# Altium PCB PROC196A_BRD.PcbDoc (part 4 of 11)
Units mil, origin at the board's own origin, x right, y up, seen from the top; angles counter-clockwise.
Board outline 3346.45 x 4921.26 mil, 8 copper layers (Top Layer, GND1, SIG1, PWR1, PWR2, SIG2, GND2, Bottom Layer), stack 54.534 mil thick; 736 components, 498 nets, 3030 pads, 1279 vias.
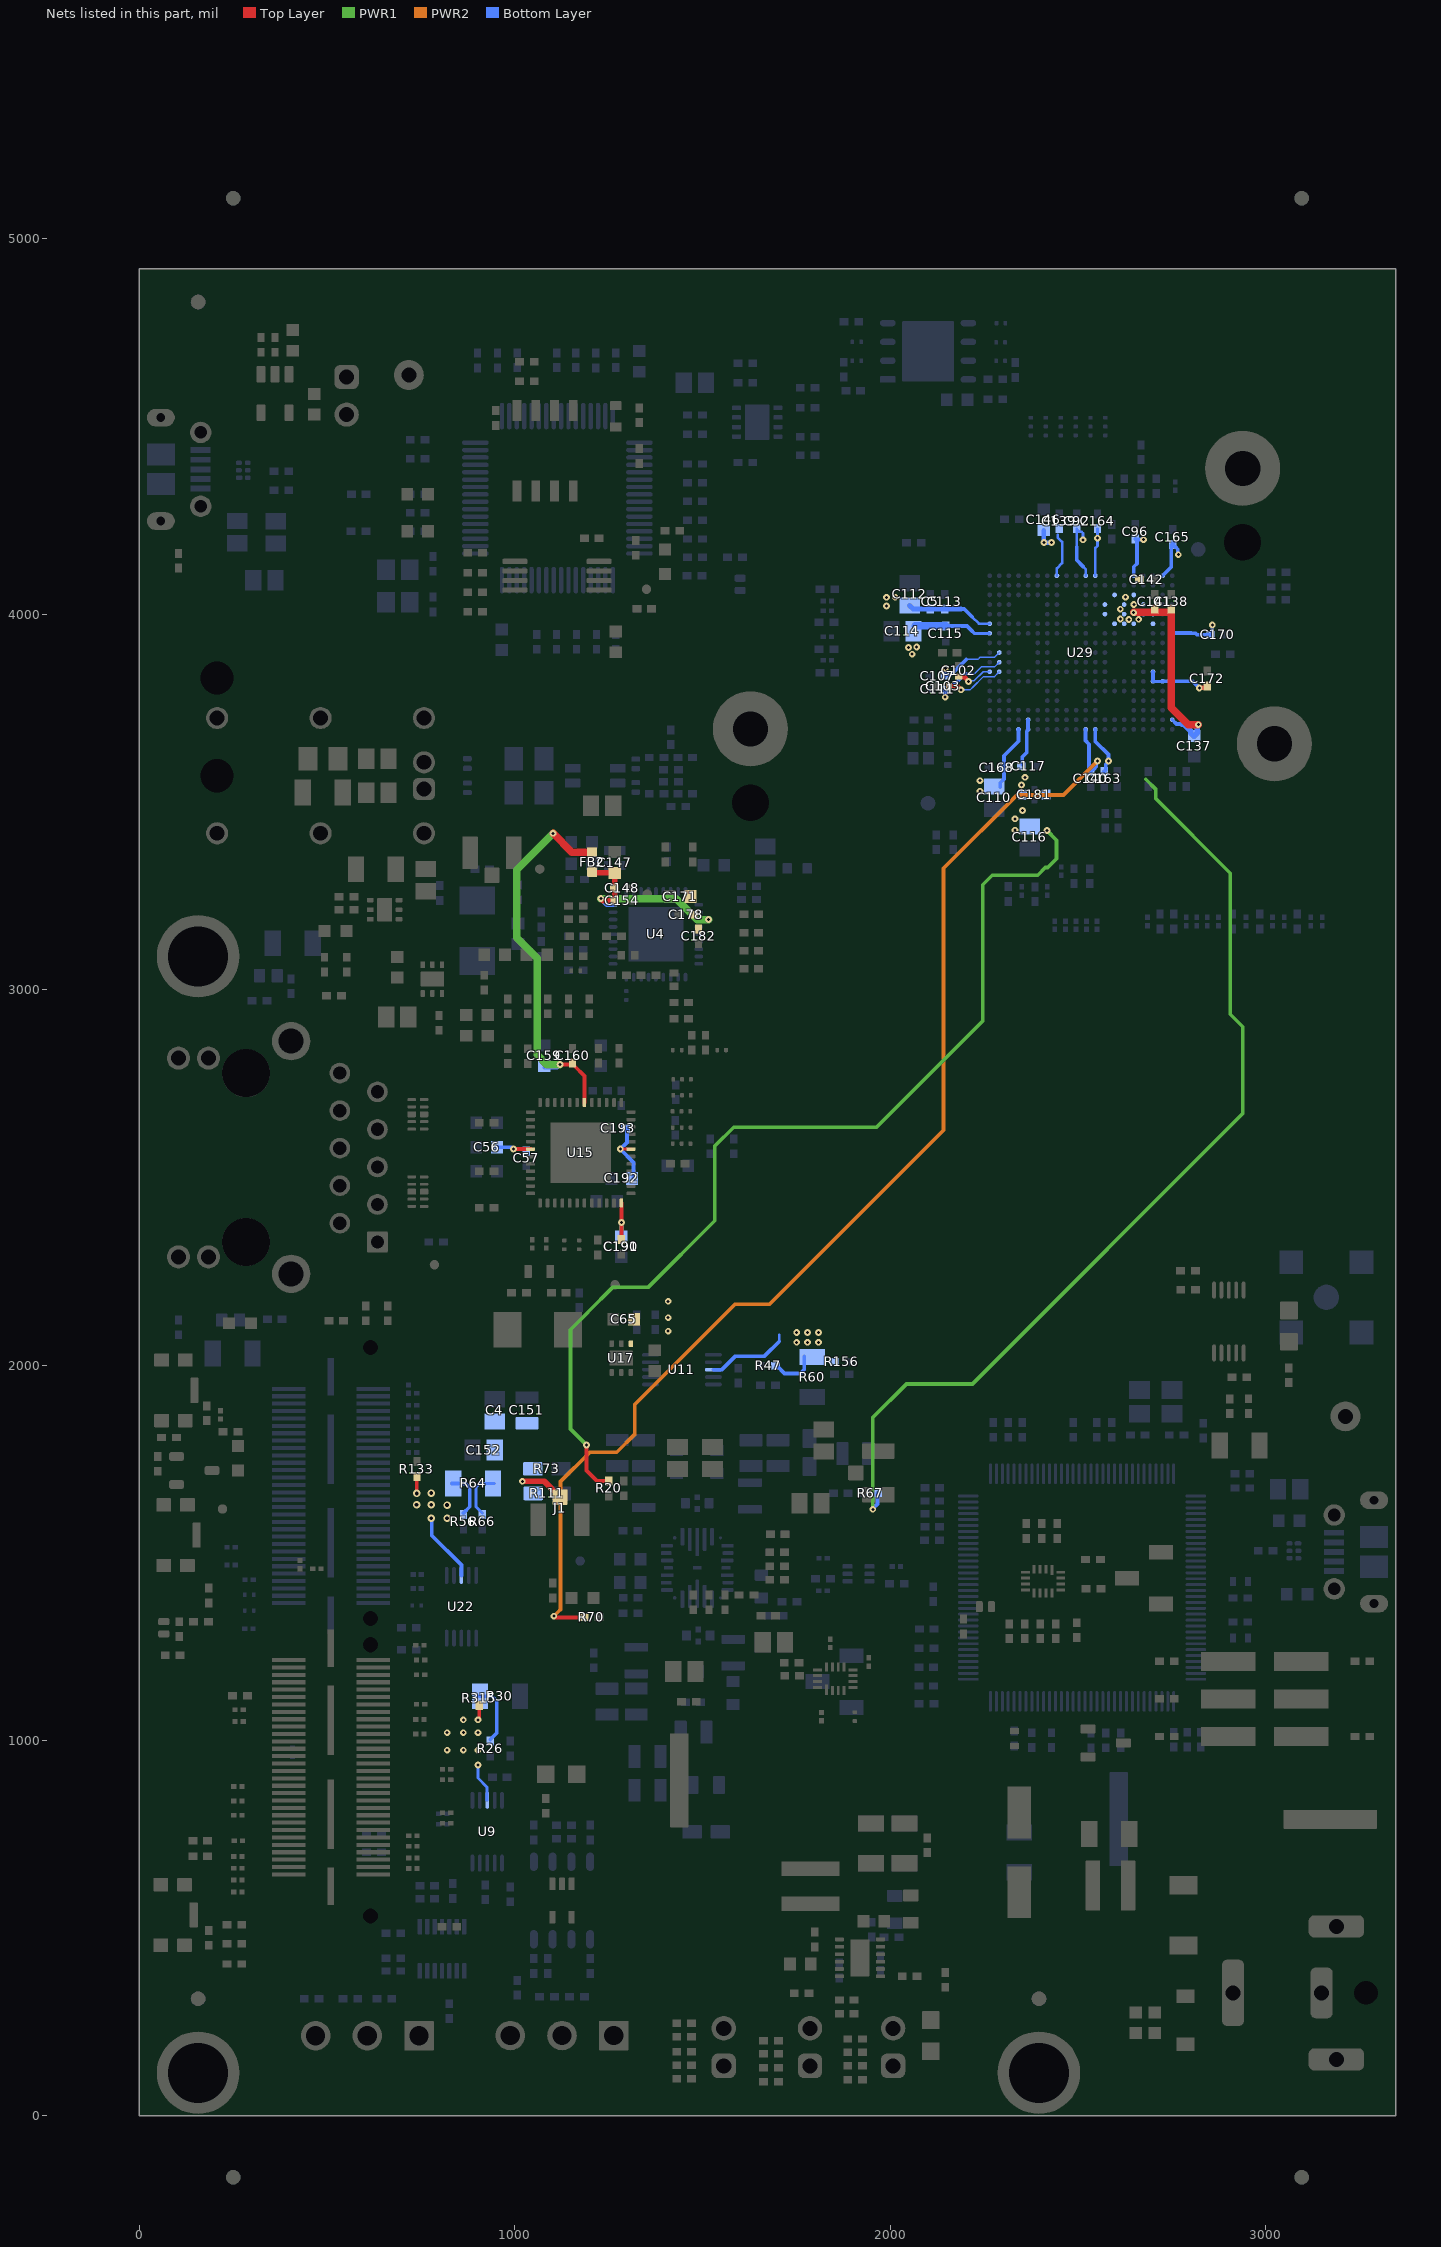
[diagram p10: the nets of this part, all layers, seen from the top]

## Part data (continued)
J9: library part CMP-0088394-1, "RJ45 Connector with 1000 Base-TX Inetgrated Magnetic", Manufacturer=LINK-PP, Operating Temperature Range="-40°C to +85°C"
J12: library part CMP-0079472-1, "DC POWER JACK, R/A, TH", Color=Black, Current_A=8A, Manufacturer="CUI Inc.", Supplier Part Number 1=CP-063AH-ND, Voltage_V=24V
J13: library part CMP-0055823-2, "Connector, SMA Jack, Vertical, Gold, SMD", Color=Gold, Manufacturer="Cinch Connectivity"
J14: library part CMP-0055788-1, "UMC Straight Jack Receptacle, 50 Ohm, Gold, SMT", Manufacturer="Cinch Connectivity", Supplier Part Number 1=J983CT-ND
J16: library part CMP-0075648-2, "Header, 2.54mm, 3x2, Gold, SMT", Color=Black, Current_A=4.9A, Manufacturer=Samtec, Supplier Part Number 1=TSM-103-01-L-DV-ND, Voltage_V=475V
J17 J18 J20 P1: library part CMP-0075405-3, "Header, 100mil, 2x1, Gold, TH", Color=Black, Current_A=6.3A, Manufacturer=Samtec, Supplier Part Number 1=SAM1029-02-ND, Voltage_V=550V
J19: library part CMP-0075524-1, "Receptacle, 0.5 mm, 30x2, Gold, TH", Color=Black, Manufacturer=Samtec, PartNumber=QSH-030-01-L-D-A, Supplier Part Number 1=SAM8180-ND
J21 J22 J23: library part CMP-0084373-1, "Header, 1x1, Gold, SMT", Color=Black, Current_A=3A, Manufacturer="Sullins Connector Solutions"
L1: library part CMP-0081093-1, "Inductor, Shielded, Metal Composite, 1.5 µH, 2.3 A, 0.11 ohm, AEC-Q200 Grade 0, SMD", Manufacturer=TDK, Supplier Part Number 1=445-174575-1-ND, Value1="0.11 ohm", Value2=2.3A, ValueDisplayed=1.5µH
L2 L8 L9: library part CMP-0091696-1, "240nH Shielded Thin Film Inductor 5A 23mOhm Max 0806 (2016 Metric)", Digikey Part Number=445-181484-1-ND, Manufacturer=TDK, Mouser Part Number=810-TFM201610ALMAR24, Operating Temperature Range="-55°C to +150°C", Test Frequency=1MHz, Tolerance_%=20%
L3 L4: library part CMP-0081523-1, "Ferrite Bead, 600 ohm @ 100 MHz, 0.3 A, 0402", Manufacturer=MuRata, Supplier Part Number 1=490-3998-1-ND, Value1="0.7 ohm", Value2=0.3A, ValueDisplayed="600 ohm"
L5: library part CMP-0089502-2, "Power Inductor (SMD), 4.7 µH, 5.1 A, Shielded, 4.5 A, XAL40xx Series, 4mm x 4mm x 3.1mm", Manufacturer=Coilcraft, Mouser Part Number=994-XAL4030-472MEC, Operating Temperature Range="to +165°C", Self Resonant Frequency=36MHz, Test Frequency=1MHz, Tolerance_%=20%
L6: library part CMP-0120010-1, "Ultra-Low Loss Shielded Power Inductors 2.2µH ±20% 7.8A 22.1mOhms", Manufacturer=Coilcraft, Value1="0.0201 ohm", Value2=6.1A, ValueDisplayed=2.2uH
L7: library part CMP-0089334-1, "200µH @ 100kHz 2 Line Common Mode Choke Surface Mount 70mA DCR 5.5Ohm", Digikey Part Number=445-174934-1-ND, Impedance At Frequency="9.5kΩ @ 10MHz", Manufacturer=TDK, Mouser Part Number=810-ACT1210L-2012P00, Operating Temperature Range="-40°C to +125°C", Test Frequency=100kHz, Tolerance_%=-10/30%
L10: library part CMP-0089947-1, "100 Ohms @ 100MHz 1 Power Line Ferrite Bead 0805 (2012 Metric) 4A 20mOhm", Digikey Part Number=445-172903-1-ND, Impedance At Frequency="100Ω @ 100MHz", Manufacturer=TDK, Mouser Part Number=810-MPZ2012S101ATD25, Operating Temperature Range="-55°C to +125°C", Test Frequency=100MHz, Tolerance_%=25%
LBL1: library part CMP-0003625-1, "Thermal Transfer Printable Labels, 0.650\" W x 0.200\" H - 10,000 per roll", Manufacturer=Brady, Supplier Part Number 1=97C5133
Logo1: library part CMP-0074838-1, "Texas Instrument Corporate Signature"
LOGO2: library part CMP-0074844-1
Logo3: library part CMP-0074847-1, "FCC_disclaimer"
Logo4: library part CMP-0074769-1
Logo5: library part CMP-0093808-1, Manufacturer="Texas Instruments", Operating Temperature Range=to
NT1: library part CMP-0078142-4, "Single point connection between nets.", Manufacturer=N/A
NT2 NT3 NT4: library part CMP-0078142-3, "Single point connection between nets.", Manufacturer=N/A
Q1: library part CMP-0000947-2, "MOSFET, N-CH, 100 V, 0.17 A, SOT-23", Alternate Manufacturer=None, Manufacturer="Fairchild Semiconductor", Supplier Part Number 1=BSS123NCT-ND, Value1=1, Value2="1.8 nC"
R1 R3 R4 R5 R6 R11 R12 R13 R14 R16 R17 R20 R21 R22 R23 R25 R27 R29 R31 R33 R35 R37 R50 R51 R54 R57 R58 R59 R61 R62 R63 R67 R70 R71 R75 R76 R78 R88 R90 R95 R107 R109 R113 R117 R128 R129 R131 R136 R146 R148 R149 R150 R151 R152 R153 R158 R160 R162 R164 R166 R167 R176 R181 R185 R186 R190 R209 R213 R214 R233 R246 R259 R269 R291 R295 R297 R316 R330 R353 R354 R355 R356 R357 R358 R359 R360 R367 R400 R401 R419: library part CMP-0026992-3, "RES, 0, 5%, 0.1 W, AEC-Q200 Grade 0, 0402", Manufacturer=Panasonic, Power_W=100mW, Supplier Part Number 1=P0.0JCT-ND, TempCo="600 ppm/C", Tolerance_%=5%, Value2=0.1W, Value_Code=0000, ValueDisplayed=0
R2: library part CMP-0026555-2, "RES, 7.50 k, 1%, 0.063 W, AEC-Q200 Grade 0, 0402", Manufacturer=Vishay-Dale, Power_W=63mW, Supplier Part Number 1=541-7.50KLCT-ND, TempCo="100 ppm/C", Tolerance_%=1%, Value2=0.063W, Value_Code=7k50, ValueDisplayed=7.50k
R7 R8 R9 R10 R18 R19 R41 R43 R46 R49 R86 R102 R106 R125 R155 R157 R177 R184 R187 R201 R210 R222 R250 R251 R264 R271 R272 R273 R283 R296 R299 R301 R303 R305 R309 R310 R312 R314 R326 R335 R350 R409 R416 R417 R418: library part CMP-0025958-3, "RES, 10.0 k, 1%, 0.063 W, AEC-Q200 Grade 0, 0402", Manufacturer=Vishay-Dale, Power_W=63mW, Supplier Part Number 1=541-10.0KLCT-ND, TempCo="100 ppm/C", Tolerance_%=1%, Value2=0.063W, Value_Code=10k0, ValueDisplayed=10.0k
R15 R24 R85 R87: library part CMP-0026491-2, "RES, 61.9, 1%, 0.063 W, AEC-Q200 Grade 0, 0402", Manufacturer=Vishay-Dale, Power_W=63mW, Supplier Part Number 1=541-61.9LCT-ND, TempCo="100 ppm/C", Tolerance_%=1%, Value2=0.063W, Value_Code=61R9, ValueDisplayed=61.9
R26 R32 R36 R47 R56 R65 R66 R268 R348 R352 R362: library part CMP-0025964-3, "RES, 10.2, 1%, 0.063 W, AEC-Q200 Grade 0, 0402", Manufacturer=Vishay-Dale, Power_W=63mW, Supplier Part Number 1=541-10.2LCT-ND, TempCo="100 ppm/C", Tolerance_%=1%, Value2=0.063W, Value_Code=10R2, ValueDisplayed=10.2
R28: library part CMP-0023343-3, "RES, 0, 1%, 0.1 W, AEC-Q200 Grade 0, 0603", Manufacturer="Stackpole Electronics Inc", Power_W=100mW, Supplier Part Number 1=RMCF0603ZT0R00CT-ND, TempCo=ppm/C, Tolerance_%=1%, Value2=0.1W, Value_Code=0
R30 R60 R64 R346: library part CMP-0017253-2, "RES, 0.001, 1%, 1 W, AEC-Q200 Grade 0, 1206", Manufacturer="Stackpole Electronics Inc", Power_W=1W, Supplier Part Number 1=CSNL1206FT1L00CT-ND, TempCo="50 ppm/C", Tolerance_%=1%, Value_Code=1L000, ValueDisplayed=0.001
R34 R205 R280 R340 R342: library part CMP-0026890-5, "RES, 2.2 k, 5%, 0.063 W, AEC-Q200 Grade 0, 0402", Manufacturer=Vishay-Dale, Power_W=63mW, Supplier Part Number 1=541-2.2KJCT-ND, TempCo="200 ppm/C", Tolerance_%=5%, Value2=0.063W, Value_Code=2k20, ValueDisplayed=2.2k
R38: library part CMP-0026395-2, "RES, 47.5 k, 1%, 0.063 W, AEC-Q200 Grade 0, 0402", Manufacturer=Vishay-Dale, Power_W=63mW, Supplier Part Number 1=541-47.5KLCT-ND, TempCo="100 ppm/C", Tolerance_%=1%, Value2=0.063W, Value_Code=47k5, ValueDisplayed=47.5k
R39 R40 R42 R44 R45 R74 R96 R98 R100 R101 R103 R105 R121 R122 R178 R195 R225 R230 R234 R237 R238 R239 R240 R245 R247 R249 R290 R325 R336 R338 R339 R369 R374 R375 R376 R377 R413: library part CMP-0089575-2, "Res Thick Film 0201 33.2 Ohm 1% 0.05W(1/20W) ±200ppm/C Pad SMD Automotive T/R", Digikey Part Number=P122945CT-ND, Manufacturer=Panasonic, Mouser Part Number=667-ERJ-1GNF33R2C, Operating Temperature Range="-55°C to +125°C", Power_W=50mW, TempCo=200ppm/°C, Tolerance_%=1%
R52: library part CMP-0026918-5, "RES, 3.3 k, 5%, 0.063 W, AEC-Q200 Grade 0, 0402", Manufacturer=Vishay-Dale, Power_W=63mW, Supplier Part Number 1=541-3.3KJCT-ND, TempCo="200 ppm/C", Tolerance_%=5%, Value2=0.063W, Value_Code=3k30, ValueDisplayed=3.3k
R53: library part CMP-0026938-5, "RES, 4.7 k, 5%, 0.063 W, AEC-Q200 Grade 0, 0402", Manufacturer=Vishay-Dale, Power_W=63mW, Supplier Part Number 1=541-4.7KJCT-ND, TempCo="200 ppm/C", Tolerance_%=5%, Value2=0.063W, Value_Code=4k70, ValueDisplayed=4.7k
R55: library part CMP-0026907-3, "RES, 33 k, 5%, 0.063 W, AEC-Q200 Grade 0, 0402", Manufacturer=Vishay-Dale, Power_W=63mW, Supplier Part Number 1=541-33KJCT-ND, TempCo="200 ppm/C", Tolerance_%=5%, Value2=0.063W, Value_Code=33k0, ValueDisplayed=33k
R68 R69: library part CMP-0026878-3, "RES, 220, 5%, 0.063 W, AEC-Q200 Grade 0, 0402", Manufacturer=Vishay-Dale, Power_W=63mW, Supplier Part Number 1=541-220JCT-ND, TempCo="200 ppm/C", Tolerance_%=5%, Value2=0.063W, Value_Code=220R, ValueDisplayed=220
R72 R80 R81 R82 R83 R84 R91 R94 R114 R115 R135 R138 R165 R168 R188 R189 R191 R192 R196 R197 R198 R212 R215 R216 R218 R219 R220 R223 R224 R226 R229 R317 R318 R319 R320 R321 R322 R323 R324 R327 R328 R329 R334 R341 R344 R345 R349 R351 R361 R363 R364 R365 R366 R370 R371 R379 R390 R391 R399 R422 R423 R424 R425: library part CMP-0027008-4, "RES, 0, 5%, 0.05 W, 0201", Manufacturer=Vishay-Dale, Power_W=50mW, Supplier Part Number 1=72M6743, TempCo=ppm/C, Tolerance_%=5%, Value2=0.05W, Value_Code=0000, ValueDisplayed=0
R73 R104 R111 R200: library part CMP-0091690-1, "RES 0 OHM JUMPER 1/4W 0603", Digikey Part Number=HCJ0603ZT0R00CT-ND, Manufacturer="Stackpole Electronics", Operating Temperature Range="-55°C to +155°C", Power_W=250mW
R77 R93 R108 R120: library part CMP-0026699-1, "RES, 470, 1%, 0.1 W, AEC-Q200 Grade 0, 0402", Manufacturer=Panasonic, Power_W=100mW, Supplier Part Number 1=P470LCT-ND, TempCo="100 ppm/C", Tolerance_%=1%, Value2=0.1W, Value_Code=470R, ValueDisplayed=470
R79 R89 R92 R97 R112 R118 R132 R137 R139 R141 R142 R143 R173 R252 R253 R254 R255 R256 R257 R258 R286 R287 R288 R289: library part CMP-0026237-2, "RES, 2.49 k, 1%, 0.063 W, AEC-Q200 Grade 0, 0402", Manufacturer=Vishay-Dale, Power_W=63mW, Supplier Part Number 1=541-2.49KLCT-ND, TempCo="100 ppm/C", Tolerance_%=1%, Value2=0.063W, Value_Code=2k49, ValueDisplayed=2.49k
R99 R123 R124 R126 R127 R133 R140 R159 R163 R315 R331 R332: library part CMP-0026071-3, "RES, 1.00 k, 1%, 0.063 W, AEC-Q200 Grade 0, 0402", Manufacturer=Vishay-Dale, Power_W=63mW, Supplier Part Number 1=541-1.00KLCT-ND, TempCo="100 ppm/C", Tolerance_%=1%, Value2=0.063W, Value_Code=1k00, ValueDisplayed=1.00k
R110 R267: library part CMP-0026827-3, "RES, 10, 5%, 0.063 W, AEC-Q200 Grade 0, 0402", Manufacturer=Vishay-Dale, Power_W=63mW, Supplier Part Number 1=541-10JCT-ND, TempCo="200 ppm/C", Tolerance_%=5%, Value2=0.063W, Value_Code=10R0, ValueDisplayed=10
R116 R199 R265 R270: library part CMP-0081856-1, "RES, 0, 0%, 0.2 W, AEC-Q200 Grade 0, 0402", Manufacturer=Vishay-Dale, Power_W=200mW, Supplier Part Number 1=541-0.0YBTR-ND, Tolerance_%=0%, Value2=0.2W, Value_Code=0
R119 R130: library part CMP-0018610-3, "RES, 1.0 M, 5%, 0.25 W, AEC-Q200 Grade 0, 1206", Manufacturer=Vishay-Dale, Power_W=250mW, Supplier Part Number 1=541-1.0MECT-ND, TempCo="200 ppm/C", Tolerance_%=5%, Value2=0.25W, Value_Code=1M00, ValueDisplayed=1.0M
R134: library part CMP-0026404-2, "RES, 49.9, 1%, 0.063 W, AEC-Q200 Grade 0, 0402", Manufacturer=Vishay-Dale, Power_W=63mW, Supplier Part Number 1=541-49.9LCT-ND, TempCo="100 ppm/C", Tolerance_%=1%, Value2=0.063W, Value_Code=49R9, ValueDisplayed=49.9
R144 R145 R147 R169 R170 R171 R179 R193 R380 R381 R386 R387 R388 R389 R392: library part CMP-0026299-2, "RES, 33.2, 1%, 0.063 W, AEC-Q200 Grade 0, 0402", Manufacturer=Vishay-Dale, Power_W=63mW, Supplier Part Number 1=541-33.2LCT-ND, TempCo="100 ppm/C", Tolerance_%=1%, Value2=0.063W, Value_Code=33R2, ValueDisplayed=33.2
R154 R242 R333: library part CMP-0026993-2, "RES, 100, 5%, 0.1 W, AEC-Q200 Grade 0, 0402", Manufacturer=Panasonic, Power_W=100mW, Supplier Part Number 1=P100JCT-ND, TempCo="200 ppm/C", Tolerance_%=5%, Value2=0.1W, Value_Code=100R, ValueDisplayed=100
R156: library part CMP-0026512-2, "RES, 6.04 k, 1%, 0.063 W, AEC-Q200 Grade 0, 0402", Manufacturer=Vishay-Dale, Power_W=63mW, Supplier Part Number 1=541-6.04KLCT-ND, TempCo="100 ppm/C", Tolerance_%=1%, Value2=0.063W, Value_Code=6k04, ValueDisplayed=6.04k
R161 R175: library part CMP-0025884-3, "RES, 0, 5%, 0.125 W, 0603", Manufacturer=Vishay/Beyschlag, Power_W=125mW, Supplier Part Number 1=MCT0603-0.0-ZZCT-ND, TempCo=ppm/C, Tolerance_%=5%, Value2=0.125W, Value_Code=0000, ValueDisplayed=0
R172: library part CMP-0025960-3, "RES, 10.5 k, 1%, 0.063 W, AEC-Q200 Grade 0, 0402", Manufacturer=Vishay-Dale, Power_W=63mW, Supplier Part Number 1=541-10.5KLCT-ND, TempCo="100 ppm/C", Tolerance_%=1%, Value2=0.063W, Value_Code=10k5, ValueDisplayed=10.5k
R174 R208: library part CMP-0078244-2, "RES, 30.0 k, 1%, 0.063 W, AEC-Q200 Grade 0, 0402", Manufacturer=Vishay-Dale, Power_W=63mW, Supplier Part Number 1=541-30.0KLCT-ND, TempCo="100 ppm/C", Tolerance_%=1%, Value2=0.063W, Value_Code=30k0, ValueDisplayed=30.0k
R180 R261 R262 R263 R266 R292 R347: library part CMP-0078212-1, "RES, 510, 5%, 0.1 W, AEC-Q200 Grade 0, 0402", Manufacturer=Panasonic, Power_W=100mW, Supplier Part Number 1=P510JCT-ND, TempCo="200 ppm/C", Tolerance_%=5%, Value2=0.1W, Value_Code=510R, ValueDisplayed=510
R182 R206 R207: library part CMP-0020442-3, "RES, 0, 5%, 0.125 W, AEC-Q200 Grade 0, 0805", Manufacturer=Vishay-Dale, Power_W=125mW, Supplier Part Number 1=541-0.0ACT-ND, TempCo="200 ppm/C", Tolerance_%=5%, Value2=0.125W, Value_Code=0000, ValueDisplayed=0
R183 R204 R278 R279: library part CMP-0025950-3, "RES, 100 k, 1%, 0.063 W, AEC-Q200 Grade 0, 0402", Manufacturer=Vishay-Dale, Power_W=63mW, Supplier Part Number 1=541-100KLCT-ND, TempCo="100 ppm/C", Tolerance_%=1%, Value2=0.063W, Value_Code=100k
R194: library part CMP-0026413-2, "RES, 4.87 k, 1%, 0.063 W, AEC-Q200 Grade 0, 0402", Manufacturer=Vishay-Dale, Power_W=63mW, Supplier Part Number 1=541-4.87KLCT-ND, TempCo="100 ppm/C", Tolerance_%=1%, Value2=0.063W, Value_Code=4k87, ValueDisplayed=4.87k
R202: library part CMP-0026403-2, "RES, 49.9 k, 1%, 0.063 W, AEC-Q200 Grade 0, 0402", Manufacturer=Vishay-Dale, Power_W=63mW, Supplier Part Number 1=541-49.9KLCT-ND, TempCo="100 ppm/C", Tolerance_%=1%, Value2=0.063W, Value_Code=49k9, ValueDisplayed=49.9k
R203: library part CMP-0026225-2, "RES, 29.4 k, 1%, 0.063 W, AEC-Q200 Grade 0, 0402", Manufacturer=Vishay-Dale, Power_W=63mW, Supplier Part Number 1=541-29.4KLCT-ND, TempCo="100 ppm/C", Tolerance_%=1%, Value2=0.063W, Value_Code=29k4, ValueDisplayed=29.4k
R211: library part CMP-0026468-2, "RES, 5.76 k, 1%, 0.063 W, AEC-Q200 Grade 0, 0402", Manufacturer=Vishay-Dale, Power_W=63mW, Supplier Part Number 1=541-5.76KLCT-ND, TempCo="100 ppm/C", Tolerance_%=1%, Value2=0.063W, Value_Code=5k76, ValueDisplayed=5.76k
R217 R221 R227 R228 R231 R232 R235 R236: library part CMP-0027021-3, "RES, 10, 5%, 0.05 W, 0201", Manufacturer="Yageo America", Power_W=50mW, Supplier Part Number 1=311-10NCT-ND, TempCo="350 ppm/C", Tolerance_%=5%, Value2=0.05W, Value_Code=10R0, ValueDisplayed=10
R243 R508 R512: library part CMP-0027280-3, "RES, 4.70 k, 1%, 0.05 W, 0201", Manufacturer=Vishay-Dale, Power_W=50mW, Supplier Part Number 1=541-4.70KAABCT-ND, TempCo="100 ppm/C", Tolerance_%=1%, Value2=0.05W, Value_Code=4k70, ValueDisplayed=4.70k
R244: library part CMP-0027015-3, "RES, 22, 5%, 0.05 W, AEC-Q200 Grade 1, 0201", Manufacturer=Panasonic, Power_W=50mW, Supplier Part Number 1=ERJ-1GNJ220C-ND, TempCo="200 ppm/C", Tolerance_%=5%, Value2=0.05W, Value_Code=22R0, ValueDisplayed=22
R248: library part CMP-0022138-4, "RES, 1.00 M, 1%, 0.1 W, AEC-Q200 Grade 0, 0603", Manufacturer=Vishay-Dale, Power_W=100mW, Supplier Part Number 1=541-1.00MHCT-ND, TempCo="100 ppm/C", Tolerance_%=1%, Value2=0.1W, Value_Code=1M00, ValueDisplayed=1.00M
R260 R274: library part CMP-0026210-2, "RES, 26.7, 1%, 0.063 W, AEC-Q200 Grade 0, 0402", Manufacturer=Vishay-Dale, Power_W=63mW, Supplier Part Number 1=541-26.7LCT-ND, TempCo="100 ppm/C", Tolerance_%=1%, Value2=0.063W, Value_Code=26R7, ValueDisplayed=26.7
R275 R281: library part CMP-0021848-2, "RES, 1.00 k, 1%, 0.25 W, 0805", Manufacturer=Panasonic, Power_W=250mW, Supplier Part Number 1=P16058CT-ND, TempCo="100 ppm/C", Tolerance_%=1%, Value2=0.25W, Value_Code=1k00, ValueDisplayed=1.00k
R276 R277: library part CMP-0026244-2, "RES, 2.94 k, 1%, 0.063 W, AEC-Q200 Grade 0, 0402", Manufacturer=Vishay-Dale, Power_W=63mW, Supplier Part Number 1=541-2.94KLCT-ND, TempCo="100 ppm/C", Tolerance_%=1%, Value2=0.063W, Value_Code=2k94, ValueDisplayed=2.94k
R282: library part CMP-0020444-3, "RES, 100 k, 5%, 0.125 W, AEC-Q200 Grade 0, 0805", Manufacturer=Vishay-Dale, Power_W=125mW, Supplier Part Number 1=541-100KACT-ND, TempCo="200 ppm/C", Tolerance_%=5%, Value2=0.125W, Value_Code=100k
R284 R285: library part CMP-0078210-2, "RES, 330 k, 1%, 0.063 W, AEC-Q200 Grade 0, 0402", Manufacturer=Vishay-Dale, Power_W=63mW, Supplier Part Number 1=541-330KLCT-ND, TempCo="100 ppm/C", Tolerance_%=1%, Value2=0.063W, Value_Code=330k
R293: library part CMP-0022443-4, "RES, 48.7 k, 1%, 0.1 W, AEC-Q200 Grade 0, 0603", Manufacturer=Vishay-Dale, Power_W=100mW, Supplier Part Number 1=541-48.7KHCT-ND, TempCo="100 ppm/C", Tolerance_%=1%, Value2=0.1W, Value_Code=48k7, ValueDisplayed=48.7k
R294: library part CMP-0022430-4, "RES, 45.3 k, 1%, 0.1 W, AEC-Q200 Grade 0, 0603", Manufacturer=Vishay-Dale, Power_W=100mW, Supplier Part Number 1=541-45.3KHCT-ND, TempCo="100 ppm/C", Tolerance_%=1%, Value2=0.1W, Value_Code=45k3, ValueDisplayed=45.3k
R298 R304 R308: library part CMP-0026542-2, "RES, 750, 1%, 0.063 W, AEC-Q200 Grade 0, 0402", Manufacturer=Vishay-Dale, Power_W=63mW, Supplier Part Number 1=541-750LCT-ND, TempCo="100 ppm/C", Tolerance_%=1%, Value2=0.063W, Value_Code=750R, ValueDisplayed=750
R300 R306 R311: library part CMP-0026557-2, "RES, 7.87 k, 1%, 0.063 W, AEC-Q200 Grade 0, 0402", Manufacturer=Vishay-Dale, Power_W=63mW, Supplier Part Number 1=541-7.87KLCT-ND, TempCo="100 ppm/C", Tolerance_%=1%, Value2=0.063W, Value_Code=7k87, ValueDisplayed=7.87k
R302 R307 R313: library part CMP-0026574-2, "RES, 82.5 k, 1%, 0.063 W, AEC-Q200 Grade 0, 0402", Manufacturer=Vishay-Dale, Power_W=63mW, Supplier Part Number 1=541-82.5KLCT-ND, TempCo="100 ppm/C", Tolerance_%=1%, Value2=0.063W, Value_Code=82k5, ValueDisplayed=82.5k
R337: library part CMP-0025975-3, "RES, 11.0 k, 1%, 0.063 W, AEC-Q200 Grade 0, 0402", Manufacturer=Vishay-Dale, Power_W=63mW, Supplier Part Number 1=541-11.0KLCT-ND, TempCo="100 ppm/C", Tolerance_%=1%, Value2=0.063W, Value_Code=11k0, ValueDisplayed=11.0k
R414: library part CMP-0089574-2, "Res Thick Film 0603 1M Ohm 1% 1/10W ±100ppm/°C Molded SMD Paper T/R", Digikey Part Number=541-5248-1-ND, Manufacturer=Vishay, Mouser Part Number=71-CRCW06031M00FKEAC, Operating Temperature Range="-55°C to +155°C", Power_W=100mW, TempCo=100ppm/°C, Tolerance_%=1%
R503: library part CMP-0083836-1, "RES, 100, 1%, 0.05 W, 0201", Manufacturer=Vishay-Semiconductor, Power_W=50mW, TempCo="100 ppm/C", Tolerance_%=1%, Value2=0.05W, Value_Code=100R, ValueDisplayed=100
S1 S2: library part CMP-0002159-2, "Slide SW, SPDT 0.1A 50VDC", CurrentRating_mA=100A, Manufacturer="Copal Electronics", Supplier Part Number 1=563-1023-1-ND
SW1 SW2 SW3: library part CMP-0002325-1, "Switch, SPST-NO, Off-Mom, 0.01 A, 32 VDC, SMD", CurrentRating_mA=10A, Manufacturer="C&K Components", Supplier Part Number 1=401-1432-2-ND
TP1 TP2 TP3 TP4 TP5 TP6 TP8: library part CMP-0078143-3, "TEST POINT.  No entry in BOM.", Manufacturer=N/A
TP7 TP9: library part CMP-0055138-1, "Test Point, Miniature, Black, TH", Color=Black, Manufacturer=Keystone, Supplier Part Number 1=36-5001-ND
U1: library part CMP-0091081-1, "3.3V Uniform Sector Dual and Quad Serial Flash SPI 64Mbit 2.7-3.6V WSON8", Frequency_Fixed=120MHz, Manufacturer=GigaDevice, Max Supply Voltage=3.6V, Min Supply Voltage=2.7V, Nominal Supply Current=13-15mA, Operating Temperature Range="-40°C to +125°C"
U2: library part CMP-0088353-1, "3.5-V to 36-V, 1.5-A, and 2.5-A Automotive Step-down Voltage Converter", Manufacturer="Texas Instruments", Max Supply Voltage=32V, Min Supply Voltage=3.5V, Nominal Supply Current=23uA, Operating Temperature Range="-40°C to +125°C", Output Voltage=3.3/5/1-20V, Switching Frequency=400/2100/250-2200kHz
U3: library part CMP-0075992-1, "Automotive Fault Protected CAN Transceiver With Flexible Data-Rate, D0008A (SOIC-8)", Alternate Manufacturer="Texas Instruments", Alternate PartNumber=TCAN1042HGVDRQ1
U4: library part CMP-0085268-1, "Low Power Auto PHY 1000BASE-T1 Automotive Ethernet Physical Layer Transceiver, RND0036A (VQFNP-36)", Alternate Manufacturer="Texas Instruments", Alternate PartNumber=DP83TG720SWRNDTQ1
U5: library part CMP-0089855-1, "Low-Power Fault Protected CAN FD Transceiver with INH and WAKE", Manufacturer="Texas Instruments", Max Supply Voltage=28V, Min Supply Voltage=1.7V, Operating Temperature Range="-40°C to +125°C"
U6: library part CMP-0029856-2, "Tiva C Series Microcontroller, 1024 KB Flash, 256 KB SRAM, 12 Bit, 20 Channels, -40 to 105 degC, 128-Pin TQFP (PDT), Green (RoHS & no Sb/Br), Tray", Manufacturer="Texas Instruments", Temperature Range="-40 to 105 degC"
U7: library part CMP-0033001-1, "Precision Micropower Shunt Voltage Reference, 0.5% accuracy, 2.5 V, 15 ppm / degC, 15 mA, -40 to 125 degC, 3-pin SOT-23 (DBZ), Green (RoHS & no Sb/Br)", Manufacturer="Texas Instruments", Rating=Catalog, Temp Coeff(Max)(ppm/ degree C)=100, Temp Coeff(Typ)(ppm/ degree C)=15
U8: library part CMP-0091078-3, "Three Buck Converters and 5-V Boost for AWR and IWR Radar Sensors", Manufacturer="Texas Instruments", Max Supply Voltage=4V, Min Supply Voltage=3V, Nominal Supply Current=3uA, Operating Temperature Range="-40°C to +150°C", Output Voltage=0.9-1.9V, Switching Frequency=4.4-8.8-17.6MHz
U9 U11 U12 U22: library part CMP-0037979-1, "High-Side Measurement, Bi-Directional Current / Power Monitor with I2C Interface, 2.7 to 5.5 V, -40 to 125 degC, 10-pin SOP (DGS10), Green (RoHS & no Sb/Br)", Manufacturer="Texas Instruments", Quiescent Current (+/-)(Typ)(mA)=0.33, Rating=Catalog
U10 U21: library part CMP-0043115-3, "4-Channel ESD Protection Array for High-Speed Data Interfaces, DRY0006A (USON-6)", Breakdown Voltage(Min)(V)=6, IO Capacitance(Typ)(pF)=1.6, IO Leakage Current(nA)=1, Manufacturer="Texas Instruments", Operating Temperature Range="-40 to 85 C", Rating=Catalog
U13 U14: library part CMP-0073613-3, "4-Channel Ultra-Low-Capacitance IEC ESD Protection Diode, DQA0010A (USON-10)", Alternate Manufacturer="Texas Instruments"
U15: library part CMP-0076013-2, "Extended Temperature Gigabit Ethernet PHY with SGMII, RGZ0048B (VQFN-48)", Alternate Manufacturer="Texas Instruments", Alternate PartNumber=DP83867ERGZT
U16: library part CMP-0036314-5, "Single Output High PSRR LDO, 500 mA, Adjustable 1.25 to 6 V Output, 2.7 to 6.5 V Input, with Low IQ, 6-pin SON (DRV), -40 to 125 degC, Green (RoHS & no Sb/Br)", Manufacturer="Texas Instruments"
U17: library part CMP-0078869-1, "Capacitor-Free, 300-mA, Low-Dropout Regulator for Automotive, DRV0006A (WSON-6)", Alternate Manufacturer="Texas Instruments"
U18: library part CMP-0004747-1, "Quad High Speed USB to Multipurpose UART/MPSSE IC", Manufacturer=FTDI, Supplier Part Number 1=768-1026-1-ND
U19: library part CMP-0081524-1, "1K Microwire Compatible Serial EEPROM, TSSOP-8", Manufacturer=Microchip, Supplier Part Number 1=93LC46B-I/ST-ND
U20: library part CMP-0036402-3, "Single Output High PSRR LDO, 1 A, Adjustable 1.2 to 5.5 V Output, 2.7 to 5.5 V Input, 8-pin SON (DRB), -40 to 125 degC, Green (RoHS & no Sb/Br)", Manufacturer="Texas Instruments"
U23 U26: library part CMP-0067415-1, "10-Ohm Quad SPDT Analog Switch, RSV0016A (UQFN-16)", Alternate Manufacturer="Texas Instruments"
U24: library part CMP-0067397-2, "1.4V-Capable +/-0.5degC Temperature Sensor with Alert Function and I2C/SMBus interface in SOT-563, DRL0006A (SOT-OTHER-6)", Alternate Manufacturer="Texas Instruments", Alternate PartNumber=TMP112AIDRLT
U27: library part CMP-0092338-1, "Linear Voltage Regulator IC Positive Fixed Output 300mA SOT-23-5", Digikey Part Number=296-TPS78417QDBVRQ1CT-ND, Dropout Voltage=900mV, Manufacturer="Texas Instruments", Max Supply Voltage=6V, Min Supply Voltage=1.65V, Mouser Part Number=595-TPS78417QDBVRQ1, Nominal Supply Current=0.033mA, Operating Temperature Range="-40°C to +150°C", Output Voltage=1.7V
U28: library part CMP-0005318-2, "2-Kb, 4-Kb, 8-Kb and 16-Kb I2C CMOS Serial EEPROM, SOIC-8", Manufacturer="ON Semiconductor", Supplier Part Number 1=CAV24C02WE-GT3OSCT-ND
U29: library part CMP-0122080-1, Manufacturer="Texas Instruments", Operating Temperature Range=to
U32: library part CMP-0051661-3, "Automotive Catalog Single Inverter, DCK0005A, LARGE T&R", F @ Nom Voltage(Max)(Mhz)=150, Generic Part Number=SN74LVC1G04-Q1, ICC @ Nom Voltage(Max)(mA)=0.01, Manufacturer="Texas Instruments", Operating Temperature Range(C)="-40 to 125", Rating=Automotive, tpd @ Nom Voltage(Max)(ns)=7.5,5.2,4.2,3.7, Voltage(Nom)(V)=1.8,2.5,3.3,5
U33: library part CMP-0860463-1, "Automotive 150-mA high-voltage ultra-low-IQ low-dropout (LDO) linear regulator, DRV0006A (WSON-6)", Alternate Manufacturer="Texas Instruments", Operating Temperature Range="-40 to 150 C", Rating=Automotive
Y1: library part CMP-0081529-1, "Crystal, 12 MHz, 15 ppm, 8 pF, AEC-Q200 Grade 1, SMD", Frequency Stability="50 ppm", Frequency Tolerance="15 ppm", Frequency_Fixed=12MHz, Load Capacitance="8 pF", Manufacturer=NDK, Supplier Part Number 1=644-1128-1-ND
Y2: library part CMP-0078214-2, "Crystal, 16 MHz, 15 ppm, 8 pF, AEC-Q200 Grade 1, SMD", Frequency Stability="150 ppm", Frequency Tolerance="10 ppm", Frequency_Fixed=16MHz, Load Capacitance="7.36 pF", Manufacturer=NDK, Supplier Part Number 1=644-1129-1-ND
Y3: library part CMP-0001431-1, "50 MHz ±15ppm Crystal 8pF 50 Ohms 4-SMD, No Lead", Digikey Part Number=644-1306-1-ND, Frequency Stability=50ppm, Frequency Tolerance=15ppm, Frequency_Fixed=50MHz, Load Capacitance=8pF, Manufacturer=NDK, Mouser Part Number=344-NX2016SA50MSTZS3, Operating Temperature Range="-40°C to +125°C"
Y4: library part CMP-0004620-3, "Crystal, 25 MHz, 18 pF, SMD", Frequency Stability=+/-30ppm, Frequency_Fixed=25MHz, Manufacturer="Abracon Corporation", Supplier Part Number 1=535-10645-1-ND
Y5: library part CMP-0004614-3, "Crystal, 25 MHz, 18 pF, SMD", Frequency_Fixed=25MHz, Frequency Stability=+/-25ppm, Manufacturer="Abracon Corporation"
ZZ1: library part CMP-0003616-3
ZZ2: library part CMP-0077236-1
ZZ3: library part CMP-0077237-1
ZZ4: library part CMP-0077238-1

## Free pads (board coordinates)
  round 1.97 on Mech16: 1(1097.78,2580.37) 1(1097.78,2596.11)
  round 7.85 on Mech16: 1(1279.65,138.71) 1(1279.65,149.55) 1(1279.65,171.19) 1(1279.65,182.03) 1(1301.33,138.71) 1(1301.33,149.55) 1(1301.33,171.19) 1(1301.33,182.03)
  round 5 on Mech16: 1(1434.44,1257.89) 1(1434.44,1257.89) 1(1434.44,1304.89) 1(1434.44,1304.89) 1(1528.02,1135.47) 1(1528.02,1328.39) 1(1532.98,1140.44) 1(1532.98,1323.42)
  round 0.25 on Mech16: 1(1490.2,2246.19) 1(1490.2,2246.19) 1(1490.2,2246.19) 1(1490.2,2246.19) 1(1490.2,5467.85) 1(1490.2,5467.85) 1(1490.2,5467.85) 1(1490.2,5467.85) 1(1608.31,2690.56) 1(1608.31,2690.56) 1(1608.31,2848.05) 1(1608.31,2848.05) 1(1627.99,3448.74) 1(1627.99,3448.74) 1(1627.99,3547.17) 1(1627.99,3547.17) 1(1627.99,3596.38) 1(1627.99,3596.38) 1(1627.99,3647.56) 1(1627.99,3647.56) 1(1627.99,3694.8) 1(1627.99,3694.8) 1(1627.99,3694.8) 1(1627.99,3742.05) 1(1627.99,3742.05) 1(1627.99,3793.23) 1(1627.99,3793.23) 1(1627.99,4255.45) 1(1627.99,4255.45) 1(1627.99,5467.85) 1(1627.99,5467.85) 1(1859.76,4895.29) 1(1864.21,2246.19) 1(1864.21,2246.19) 1(1864.21,3356.36) 1(1864.21,3356.36) 1(1879.45,4875.6) 1(1879.45,4914.97) 1(1899.13,4895.29) 1(2014.1,4895.29) 1(2033.78,4875.6) 1(2033.78,4914.97) 1(2053.47,4895.29) 1(2095.99,2926.79) 1(2115.67,2907.1) 1(2115.67,2946.47) 1(2123.62,3615.76) 1(2123.62,3615.76) 1(2123.62,3759.82) 1(2123.62,3759.82) 1(2135.36,2926.79) 1(2193.34,3818.99) 1(2193.34,3813.05) 1(2193.34,3813.05) 1(2193.34,3818.99) 1(2193.79,3805.53) 1(2193.79,3805.53) 1(2193.93,4023.89) 1(2193.93,4029.8) 1(2193.93,4023.89) 1(2193.93,4029.8) 1(2197.68,3841.96) 1(2197.68,3841.96) 1(2199.51,3757.88) 1(2199.51,3757.88) 1(2199.6,3754.32) 1(2199.6,3756.47) 1(2199.6,3756.47) 1(2199.6,3754.32) 1(2209.69,3872.64) 1(2209.69,3872.64) 1(2210.5,3876.46) 1(2210.5,3876.46) 1(2212.26,3919.67) 1(2212.26,3919.67) 1(2212.27,3924.8) 1(2212.27,3920.15) 1(2212.27,3920.15) 1(2212.27,3924.8) 1(2213.98,3939.35) 1(2213.98,3939.35) 1(2216.06,3975.95) 1(2216.06,3975.95) 1(2219.89,3964.24) 1(2219.89,3964.24) 1(2232.71,3813.05) 1(2232.71,3818.99) 1(2232.71,3818.99) 1(2232.71,3813.05) 1(2232.88,3810.23) 1(2232.88,3810.23) 1(2233.3,4023.89) 1(2233.3,4029.8) 1(2233.3,4023.89) 1(2233.3,4029.8) 1(2234.34,3827.6) 1(2234.34,3827.6) 1(2238.88,3760.24) 1(2238.88,3760.24) 1(2238.97,3754.32) 1(2238.97,3758.83) 1(2238.97,3758.83) 1(2238.97,3754.32) 1(2248.86,3864.68) 1(2248.86,3864.68) 1(2249.68,3868.99) 1(2249.68,3870.47) 1(2249.68,3870.47) 1(2249.68,3868.99) 1(2249.7,3871.43) 1(2249.7,3871.43) 1(2251.63,3918.86) 1(2251.63,3918.86) 1(2251.64,3919.34) 1(2251.64,3919.34) 1(2251.64,3924.8) 1(2251.64,3924.8) 1(2252.02,4092.59) 1(2252.02,4092.6) 1(2252.03,4000.78) 1(2252.03,4000.78) 1(2252.28,3930.26) 1(2252.28,3930.26) 1(2255.14,4093.27) 1(2255.14,4093.27) 1(2256.92,4053.42) 1(2256.92,4053.42) 1(2258.67,4053.42) 1(2258.67,4053.42) 1(2259.46,3995.71) 1(2259.46,3995.71) 1(2262.59,3691.33) 1(2262.59,3691.33) 1(2262.59,3730.7) 1(2262.59,3730.7) 1(2262.72,4054.13) 1(2262.72,4054.13) 1(2262.81,3990.61) 1(2262.81,3990.61) 1(2263.37,3691.33) 1(2263.37,3691.33) 1(2264.43,3981.4) 1(2264.43,3981.4) 1(2265.28,3691.17) 1(2265.28,3691.17) 1(2266.58,3730.7) 1(2266.58,3730.7) 1(2268.28,4098.06) 1(2268.28,4098.06) 1(2268.5,3730.54) 1(2268.5,3730.54) 1(2268.75,3690.61) 1(2268.75,3690.6) 1(2275.82,4106.88) 1(2275.82,4106.88) 1(2278.28,3681.84) 1(2278.28,3681.84) 1(2283.58,4041.77) 1(2294.79,3726.22) 1(2294.79,3726.22) 1(2299.35,4067.49) 1(2299.35,4067.49) 1(2300.21,4067.78) 1(2300.22,4067.78) 1(2302.95,3720.73) 1(2302.95,3720.73) 1(2307.6,4074.72) 1(2307.6,4074.72) 1(2313.19,4088.99) 1(2313.19,4088.99) 1(2314.01,4093.3) 1(2314.01,4094.76) 1(2314.01,4093.3) 1(2314.01,4094.76) 1(2314.01,3702.66) 1(2314.01,3702.66) 1(2315.75,3696.74) 1(2315.75,3696.74) 1(2325.96,3674.95) 1(2327.48,2926.79) 1(2330.73,4157.37) 1(2330.73,4157.36) 1(2332.6,3885.45) 1(2332.6,3885.45) 1(2332.6,3911.04) 1(2332.6,3911.04) 1(2334.13,4158.27) 1(2334.13,4158.27) 1(2337.63,4118.38) 1(2337.63,4118.38) 1(2338.65,4118.38) 1(2338.65,4118.38) 1(2339.36,3634.24) 1(2339.36,3673.61) 1(2339.36,3673.62) 1(2339.36,3634.25) 1(2343.35,4119.35) 1(2343.35,4119.35) 1(2345.28,3634.24) 1(2345.28,3634.24) 1(2345.28,3673.61) 1(2345.28,3673.61) 1(2347.17,2907.1) 1(2347.17,2946.47) 1(2347.36,3673.71) 1(2347.36,3673.71) 1(2350.81,3634.49) 1(2350.81,3634.49) 1(2354.65,3760.84) 1(2354.65,3760.84) 1(2354.65,3805.33) 1(2354.65,3805.33) 1(2354.65,3991.16) 1(2354.65,3991.16) 1(2354.65,4035.64) 1(2354.65,4035.64) 1(2361.75,4170.26) 1(2361.75,4170.26) 1(2366.85,2926.79) 1(2377.09,3885.45) 1(2377.09,3911.04) 1(2377.09,3885.45) 1(2377.09,3911.04) 1(2377.42,4134.14) 1(2377.42,4134.14) 1(2380.63,3760.84) 1(2380.63,3760.84) 1(2380.63,3805.33) 1(2380.63,3805.33) 1(2380.63,3991.16) 1(2380.63,3991.16) 1(2380.63,4035.64) 1(2380.63,4035.64) 1(2386.83,4136.09) 1(2386.83,4175.46) 1(2386.83,4175.47) 1(2386.83,4136.09) 1(2390.53,3677.51) 1(2390.53,3677.51) 1(2391.56,3677.55) 1(2391.56,3677.55) 1(2392.26,3638.14) 1(2392.26,3638.14) 1(2392.76,4175.46) 1(2392.76,4136.09) 1(2392.76,4136.09) 1(2392.76,4175.46) 1(2393.29,3638.18) 1(2393.29,3638.18) 1(2396.47,3638.18) 1(2396.47,3638.18) 1(2396.47,3677.55) 1(2396.47,3677.55) 1(2396.76,4135.75) 1(2396.76,4135.75) 1(2397.51,3677.57) 1(2397.51,3677.57) 1(2399.24,3638.24) 1(2399.24,3638.24) 1(2399.92,4895.29) 1(2403.43,4174.56) 1(2403.43,4174.56) 1(2419.61,4875.6) 1(2419.61,4914.97) 1(2439.29,4895.29) 1(2441.39,3679.51) 1(2441.39,3679.51) 1(2441.91,3679.52) 1(2441.91,3679.52) 1(2441.91,3640.12) 1(2441.91,3640.12) 1(2442.26,3640.14) 1(2442.26,3640.14) 1(2442.78,3640.15) 1(2442.78,3640.15) 1(2443.13,3640.15) 1(2443.13,3640.15) 1(2447.33,3640.15) 1(2447.33,3679.52) 1(2447.33,3679.52) 1(2447.33,3640.15) 1(2453.38,4126.03) 1(2453.38,4126.03) 1(2455.38,4125.86) 1(2455.38,4125.86) 1(2456.73,4165.4) 1(2456.73,4165.4) 1(2457.01,3888.79) 1(2457.01,3888.79) 1(2457.01,3933.28) 1(2457.01,3933.28) 1(2458.73,4165.23) 1(2458.73,4165.23) 1(2459.3,4125.86) 1(2459.3,4125.86) 1(2459.3,4165.23) 1(2459.3,4165.23) 1(2460.55,3783.08) 1(2460.55,3808.68) 1(2460.55,4014.75) 1(2460.55,4040.34) 1(2460.55,3783.08) 1(2460.55,3808.68) 1(2460.55,4014.75) 1(2460.55,4040.34) 1(2462.26,3684.84) 1(2462.27,3684.84) 1(2467.38,4124.43) 1(2467.38,4124.43) 1(2480.85,4161.43) 1(2480.85,4161.43) 1(2482.99,3888.79) 1(2482.99,3888.79) 1(2482.99,3933.28) 1(2482.99,3933.28) 1(2483.75,3702.38) 1(2483.75,3702.38) 1(2484.07,3651.97) 1(2484.07,3651.97) 1(2494.96,4156.29) 1(2494.96,4156.29) 1(2496.25,3703.91) 1(2496.25,3703.91) 1(2499.6,3650.41) 1(2499.6,3650.41) 1(2504.56,4110.9) 1(2504.56,4110.9) 1(2505.04,3783.08) 1(2505.04,3808.68) 1(2505.04,4014.75) 1(2505.04,4040.34) 1(2505.04,3783.08) 1(2505.04,3808.68) 1(2505.04,4014.75) 1(2505.04,4040.34) 1(2507.19,4158.88) 1(2507.19,4158.88) 1(2508.18,4159.84) 1(2508.19,4159.84) 1(2516.69,3694.28) 1(2516.69,3694.29) 1(2516.79,4113.49) 1(2516.79,4113.49) 1(2523.02,3686.83) 1(2523.02,3686.83) 1(2535.48,4131.46) 1(2535.48,4131.46) 1(2536.39,3631.01) 1(2536.39,3631.01) 1(2540.09,3629.8) 1(2540.09,3629.8) 1(2545.74,3669.68) 1(2545.74,3669.68) 1(2545.87,3669.68) 1(2545.87,3669.68) 1(2551.33,3668.34) 1(2551.33,3668.34) 1(2551.85,4177.43) 1(2551.85,4138.06) 1(2551.85,4138.06) 1(2551.85,4177.43) 1(2554.25,4895.29) 1(2557.77,4138.06) 1(2557.77,4177.43) 1(2557.77,4138.05) 1(2557.77,4177.42) 1(2566.95,3615.79) 1(2566.95,3615.79) 1(2573.94,4875.6) 1(2573.94,4914.97) 1(2578.66,2946.47) 1(2581.08,3974.04) 1(2581.08,3974.04) 1(2581.39,4114.43) 1(2581.39,4109.81) 1(2581.39,4109.81) 1(2581.39,4114.43) 1(2581.46,4108.52) 1(2581.46,4108.52) 1(2584.96,3735.25) 1(2584.96,3735.25) 1(2584.96,3779.74) 1(2584.96,3779.74) 1(2585,3988.24) 1(2585,3988.24) 1(2585.15,3650.7) 1(2585.15,3650.7) 1(2585.86,3994.54) 1(2585.86,4000.08) 1(2585.86,4000.08) 1(2585.86,3994.54) 1(2585.86,4000.48) 1(2585.86,4000.48) 1(2587.29,4055.42) 1(2587.29,4055.42) 1(2587.42,4046.1) 1(2587.42,4046.1) 1(2587.43,4046.91) 1(2587.43,4046.91) 1(2587.43,4052.84) 1(2587.43,4052.84) 1(2588.5,3859.86) 1(2588.5,3859.86) 1(2588.5,3885.45) 1(2588.5,3885.45) 1(2591.66,3959.11) 1(2591.66,3959.11) 1(2593.62,4895.29) 1(2596.08,3648.02) 1(2596.08,3608.65) 1(2596.08,3648.02) 1(2596.08,3608.65) 1(2596.87,3958.76) 1(2596.87,3958.76) 1(2597.66,3958.73) 1(2597.66,3958.73) 1(2602.01,3608.65) 1(2602.01,3648.02) 1(2602.01,3648.02) 1(2602.01,3608.65) 1(2602.8,3958.73) 1(2602.8,3958.73) 1(2603.89,3958.71) 1(2603.89,3958.71) 1(2610.95,3735.25) 1(2610.95,3735.25) 1(2610.95,3779.74) 1(2610.95,3779.74) 1(2616.92,3653.32) 1(2616.92,3653.32) 1(2620.76,4114.43) 1(2620.76,4111.96) 1(2620.76,4111.96) 1(2620.76,4114.43) 1(2620.83,4110.67) 1(2620.83,4110.67) 1(2625.54,4008.8) 1(2625.54,4008.8) 1(2626.43,4059.72) 1(2626.43,4059.72) 1(2626.77,4044.76) 1(2626.77,4044.76) 1(2626.8,4046.91) 1(2626.8,4046.91) 1(2626.8,4052.84) 1(2626.8,4052.84) 1(2632.99,3859.86) 1(2632.99,3885.45) 1(2632.99,3859.86) 1(2632.99,3885.45) 1(2636.8,3996.6) 1(2636.8,3996.6) 1(2641.77,3622.78) 1(2641.77,3622.78) 1(2645.68,3956.78) 1(2645.68,3956.78) 1(2646.23,3956.76) 1(2646.23,3956.76) 1(2646.23,3996.16) 1(2646.23,3996.16) 1(2646.59,3996.15) 1(2646.59,3996.15) 1(2647.14,3996.13) 1(2647.14,3996.13) 1(2647.5,3996.13) 1(2647.5,3996.13) 1(2647.53,3678.22) 1(2647.53,3678.22) 1(2651.62,3996.14) 1(2651.62,3956.76) 1(2651.62,3956.77) 1(2651.62,3996.13) 1(2654.12,3680.84) 1(2654.12,3680.84) 1(2663.96,3683.79) 1(2663.96,3683.79) 1(2664.65,3641.4) 1(2664.65,3641.4) 1(2666.83,3951.21) 1(2666.83,3951.21) 1(2669,3643.64) 1(2669,3643.64) 1(2675.67,3799.39) 1(2675.67,3799.39) 1(2683.2,3649.45) 1(2683.2,3649.45) 1(2683.46,3815.46) 1(2683.46,3815.46) 1(2684.73,3778.31) 1(2684.73,3778.31) 1(2686.28,3773.12) 1(2686.28,3773.12) 1(2689.74,3931.93) 1(2689.74,3931.93) 1(2690.77,3765.78) 1(2690.77,3765.78) 1(2692.19,3981.33) 1(2692.19,3981.33) 1(2696.4,3929.19) 1(2696.4,3929.19) 1(2698.05,3702.9) 1(2698.05,3702.9) 1(2698.27,3819.44) 1(2698.27,3819.44) 1(2698.54,3759.89) 1(2698.54,3759.89) 1(2703.74,3704.4) 1(2703.74,3704.4) 1(2704.98,3757.51) 1(2704.98,3757.51) 1(2707.36,3968.56) 1(2707.36,3968.56) 1(2710.17,3664.56) 1(2710.17,3664.56) 1(2711.73,3966.24) 1(2711.73,3966.24) 1(2713.98,3665.9) 1(2713.98,3665.9) 1(2715.77,3842.26) 1(2715.77,3842.26) 1(2715.77,3847.64) 1(2715.77,3847.64) 1(2715.79,3848.18) 1(2715.79,3848.18) 1(2718.11,3898.64) 1(2718.11,3898.64) 1(2718.13,3905.65) 1(2718.14,3899.72) 1(2718.14,3899.72) 1(2718.14,3905.65) 1(2727.19,3728.02) 1(2727.19,3733.93) 1(2727.2,3728.02) 1(2727.2,3733.93) 1(2736.79,4094.4) 1(2736.79,4094.4) 1(2739.9,3801.17) 1(2741.71,3784.07) 1(2741.71,3784.07) 1(2755.14,3842.26) 1(2755.14,3842.26) 1(2755.14,3846.37) 1(2755.14,3846.37) 1(2755.14,3846.73) 1(2755.14,3846.73) 1(2755.16,3847.28) 1(2755.16,3847.28) 1(2755.17,3847.64) 1(2755.17,3847.64) 1(2757.44,3896.83) 1(2757.44,3896.83) 1(2757.5,3905.65) 1(2757.51,3899.72) 1(2757.51,3899.72) 1(2757.51,3905.65) 1(2766.56,3728.02) 1(2766.57,3733.93) 1(2766.57,3728.02) 1(2766.57,3733.93) 1(2825.39,4284.47) 1(2825.39,4284.47) 1(2825.39,5467.85) 1(2825.39,5467.85) 1(2908.86,3540.48) 1(2908.86,3540.48) 1(2908.86,3768.4) 1(2908.86,3768.4) 1(2939.16,4142.68) 1(2939.16,4142.68) 1(2939.16,4241.11) 1(2939.16,4241.11) 1(2939.16,4290.32) 1(2939.16,4290.32) 1(2939.16,4341.5) 1(2939.16,4341.5) 1(2939.16,4388.75) 1(2939.16,4388.75) 1(2939.16,4388.75) 1(2939.16,4435.99) 1(2939.16,4435.99) 1(2939.16,4487.17) 1(2939.16,4487.17) 1(2981.54,4021.92) 1(3023.92,3556.67) 1(3023.92,3556.67) 1(3023.92,3612.77) 1(3023.92,3612.77) 1(3023.92,3655.1) 1(3023.92,3655.1) 1(3023.92,3655.1) 1(3023.92,3697.42) 1(3023.92,3697.42) 1(3023.92,3753.52) 1(3023.92,3753.52) 1(3061.61,3540.48) 1(3061.61,3540.48) 1(3061.61,5271) 1(3061.61,5271) 1(3061.61,5428.48) 1(3061.61,5428.48) 1(3179.73,5467.85) 1(3179.73,5467.85) 1(3179.73,5467.85) 1(3179.73,5467.85)
  round 4.25 on Mech16: 1(2373.93,1690.63)
  round 0.05 on Mech16: 1(2572.23,3956.77) 1(2572.23,3956.76)
  round 220 hole 160: ""(156.55,114.56) ""(156.55,3089.06) ""(2396.55,114.56)
  round 93 hole 98 unplated: ""(1627.99,3497.95) ""(2939.16,4191.9)
  round 200 hole 94.02 mask+0: ""(1627.99,3694.8) ""(2939.17,4388.74) ""(3023.94,3655.12)

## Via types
v1: diameter 18, hole 8, Top Layer to Bottom Layer, tented both sides, 1230 vias
v2: diameter 19.68, hole 7.87, Top Layer to Bottom Layer, 30 vias
v3: diameter 20, hole 10, Top Layer to Bottom Layer, tented both sides, 11 vias
v4: diameter 10, hole 4, SIG2 to Bottom Layer, tented both sides, 6 vias
v5: diameter 19.68, hole 7.87, Top Layer to Bottom Layer, tented both sides, 2 vias

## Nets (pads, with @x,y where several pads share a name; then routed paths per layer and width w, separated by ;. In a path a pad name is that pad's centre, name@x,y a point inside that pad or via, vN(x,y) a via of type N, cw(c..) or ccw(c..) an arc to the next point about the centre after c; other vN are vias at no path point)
1V0: C114.1 C115.2 C116.1 C117.2 C181.1 C181.3 R20.2 R56.1 R64.2 R133.2 U22.8 U29.A5 U29.B5 U29.L1 | length 3383.6
  Top Layer w10: v3(738.91,1657.99) 739.23,1658.3 739.23,1702.98 R133.2@739.54,1703.3 ; v1(1191,1786.81) 1191,1719.16 1219.15,1691.01 R20.2@1250.68,1691.01
  PWR1 w10: v1(1191,1786.81) 1148.49,1829.32 1148.49,2094.2 1194.52,2140.23 1194.52,2140.7 1261.47,2207.65 1356.44,2207.65 1533.09,2384.3 1533.09,2583.59 1583.31,2633.81 1964.01,2633.81 2247,2916.81 2247,3279.81 2272.38,3305.19 2393.13,3305.19 2413.52,3325.58 2420.21,3325.58 2443.6,3348.97 2443.6,3398.38 v1(2417.94,3424.04)
  Bottom Layer w8: 2217.96,3955.53 2218.62,3954.87 2224.06,3949.43 U29.L1@2265.3,3949.43
  Bottom Layer w10: v3@779.04,1591.82 779.04,1546 857.87,1467.17 U22.8@857.87,1439.7 ; R64.2@832.13,1684.62 R64.2@836.07,1684.62 869.43,1684.62 879.99,1674.07 879.99,1622.35 R56.1@863.5,1605.86 ; C115.2@2148.52,3968.64 2204.85,3968.64 2217.96,3955.53 ; C117.2@2352,3600.08 2352,3619.81 2363.98,3631.79 2363.98,3688.83 2367.66,3692.52 U29.A5@2367.66,3693.52 U29.B5@2367.66,3719.11
  Bottom Layer w20: C114.1@2067.31,3969.07 2148.36,3969.07 2148.52,3968.92 C115.2@2148.52,3968.64
  other v1: 2332.74,3425.04 2332.74,3455.44 2352.84,3477.44 2349.84,3545.44 2359.72,3565.93 2059,3894 2049,3912 2071,3913
  other v3: 777.37,1591.82 819.58,1591.82 819.58,1627.21 738.59,1628.1 777.37,1628.1 777.37,1659.11
1V0_ETH: C56.1 C57.1 C65.1 C159.1 C160.1 C190.1 C191.1 C192.1 C193.1 FB2.1 U15.6 U15.24 U15.31 U15.42 U17.1 | length 1479.7
  Top Layer w8: v1(1281.2,2575.38) U15.31@1309.79,2575.38
  Top Layer w10: v1(997.01,2575.38) U15.6@1042.07,2575.38 ; v1(1120.52,2800.53) 1149.97,2800.53 C160.1@1153.91,2804.47 1158.75,2799.62 1158.75,2797.26 1185.77,2770.24 U15.42@1185.77,2699.4 ; C191.1@1284.2,2338.94 v1(1284.2,2380.16) U15.24@1284.2,2431.68
  Top Layer w20: v1(1102.23,3416.72) 1152.23,3366.72 FB2.1@1206.02,3366.72
  PWR1 w20: v1(1102.23,3416.72) 1005,3319.49 1005,3138.96 1059.65,3084.31 1059.65,2826.2 1085.32,2800.53 v1(1120.52,2800.53)
  Bottom Layer w10: C56.1@956.53,2580.18 992.21,2580.18 v1(997.01,2575.38) 997.67,2574.72 C57.1@1030.83,2574.72 ; C159.1@1078.54,2792.53 1112.52,2792.53 v1(1120.52,2800.53) ; C190.1@1284.2,2346.81 v1(1284.2,2380.16) ; C193.1@1298.94,2630.46 1298.94,2593.13 v1(1281.2,2575.38) 1316.51,2540.07 C192.1@1316.51,2497.07
  other v1: 1408.92,2090.14 1408.92,2126.16 1408.92,2169.91
1V0_ETH2: C147.1 C148.1 C154.1 C171.1 C178.1 C182.1 FB2.2 U4.9 U4.21 | length 551.2
  Top Layer w15: FB2.2@1206.02,3313.57 1208.25,3311.34 C147.1@1266.14,3311.34 C148.1@1266.14,3270.67 1266.14,3237.19 C154.1@1266.59,3236.75 1235.23,3236.75 v1(1229.31,3242.67)
  PWR1 w20: v1(1229.31,3242.67) 1430.4,3242.67 1486.13,3186.94 v1(1516.38,3186.94)
  Bottom Layer w10: U4.21@1490.38,3186.94 v1(1516.38,3186.94)
  Bottom Layer w13: v1(1229.31,3242.67) 1245.68,3226.31 U4.9@1262.03,3226.31
1V0_FILTERED: C4.1 C151.1 C152.1 J1.1 R64.1 R66.1 R73.2 R111.2 | length 246.6
  Top Layer w15: v1(1020.23,1690.41) 1078.8,1690.41 J1.1@1120.81,1648.4
  Bottom Layer w8: R66.1@913.54,1605.86 897.44,1621.96 897.44,1674.95 907.12,1684.62 R64.1@942.37,1684.62 R64.1@946.31,1684.62
1V2: C92.2 C96.2 C137.2 C138.2 C139.2 C140.2 C141.2 C142.2 C146.2 R26.1 R30.2 R70.2 R315.2 U9.8 U29.A11 U29.B20 U29.M14 U29.M15 U29.M16 U29.M18 U29.N13 U29.N15 U29.N17 U29.N18 U29.P13 U29.P15 U29.P17 U29.R14 U29.R16 U29.U8 U29.U11 U29.U16 | length 4617.9
  Top Layer w10: v1(902,1054.81) 905.35,1058.16 R315.2@905.35,1092.84 ; v1(1104,1331) 1106.16,1331 1109.35,1327.81 R70.2@1184.67,1327.81
  Top Layer w20: v1@2648.85,4005.81 2749.31,4005.81 2749.31,3751.19 2794.5,3706 v1(2821.23,3706)
  PWR2 w10: v1(1104,1331) 1116,1343 1116.14,1343 1122,1348.86 1122,1689.53 1200.28,1767.81 1271.81,1767.81 1320,1816 1320,1895.47 1586.53,2162 1678.99,2162 2142.53,2625.54 2142.53,3323.51 2337.83,3518.81 2462,3518.81 v1(2552.23,3609.05)
  Bottom Layer w7: U29.U8@2444.43,4102.97 2444.43,4122.48 2458.23,4136.27 2458.23,4192.77 2447,4204 2447,4211.81 ; 2497.58,4180 C92.2@2497.58,4226.49 ; C92.2@2497.58,4228.46 C92.2@2497.58,4226.49 ; v1(2514.04,4198.7) 2514.04,4216.05 2509.94,4220.15 2503.92,4220.15 C92.2@2497.58,4226.49 ; 2514.11,4127.7 2521.21,4120.6 U29.U11@2521.21,4102.97
  Bottom Layer w8: v1(902,934.81) 902,899.65 926.74,874.91 U9.8@926.74,840.58
  Bottom Layer w10: R30.2@903.47,1117.62 R30.2@907.41,1117.62 939.08,1117.62 951.98,1104.73 ; R26.1@934.47,1002.01 951.98,1019.52 951.98,1104.73 ; 951.98,1105.08 951.98,1104.73 ; 2497.58,4180 2497.58,4144.23 2514.11,4127.7 ; U29.A11@2521.21,3693.52 2520.62,3692.94 2520.62,3663.56 2530.02,3654.16 2530.02,3593.75 2530.2,3593.57 2530.2,3585.93 C140.2@2535.04,3581.08 2535.04,3583.05 2539.88,3587.89 2543.38,3587.89 2549.24,3593.75 2549.24,3603.88 2552.23,3606.88 v1(2552.23,3609.05) ; U29.U16@2649.16,4102.97 2649.16,4126.56 2657.6,4135 2657.6,4196.31 C96.2@2653.45,4200.46 2654.18,4199.73 2674.15,4199.73 v1(2674.88,4199) ; U29.B20@2751.52,3719.11 2762.63,3708 2777.67,3708
  Bottom Layer w12: C146.2@2408.92,4224.57 2409.51,4223.98 2409.51,4191.7 v1(2410.1,4191.11) 2410.21,4191.21 2430.21,4191.21 v1(2430.32,4191.31)
  Bottom Layer w15: 2777.67,3708 2781.92,3708 2800.69,3689.24 2800.69,3683.81 2808.94,3675.56 C137.2@2809.92,3675.56 ; C137.2@2814.88,3680.52 2815.28,3680.52 2818.57,3683.81 2818.57,3702.52 2821.23,3705.19 v1(2821.23,3706)
  other v1: 820.21,973.89 862.99,973.89 902,973.89 820.21,1020.69 862.99,1020.69 902,1020.69 862.99,1054.81 2635.83,3986 2662.39,3986.68 2613.21,3987.81 2648.85,4004.29 2613.16,4013.81 2649.16,4026.2 2626.87,4045.81
1V4_APLL: C103.1 U29.G2 | length 157.9
  Top Layer w12: C103.1@2156.75,3807.81 2180,3807.81 v1(2189,3798.81)
  Bottom Layer w4: v1(2189,3798.81) 2213,3798.81 2217.96,3803.77 2218.62,3804.43 2248.54,3834.35 2278.17,3834.35 U29.G2@2290.89,3847.07
1V4_SYNTH: C102.1 U29.G1 | length 100.1
  Top Layer w12: C102.1@2182.53,3834.24 2184.31,3832.47 2198.77,3832.47 2208.89,3822.34 v1(2208.89,3820.81)
  Bottom Layer w4: v1(2208.89,3820.81) 2211.57,3823.49 2217.96,3823.49 2218.62,3823.49 2224.4,3823.49 2247.98,3847.07 U29.G1@2265.3,3847.07
1V8: C5.2 C107.2 C110.1 C111.2 C112.1 C113.2 C163.2 C164.2 C165.2 C168.2 C170.2 C172.2 R47.1 R60.2 R67.2 R156.2 U11.8 U29.A4 U29.A12 U29.F18 U29.F19 U29.F20 U29.G18 U29.H2 U29.J2 U29.L20 U29.M1 U29.U12 U29.U19 | length 4465.7
  Top Layer w10: C172.2@2847.21,3803.87 C172.2@2847.34,3804
  Top Layer w12: v1(2823.89,3803.87) C172.2@2847.21,3803.87
  PWR1 w10: v1(1954,1615.81) 1954,1860.36 2043.56,1949.92 2219.72,1949.92 2939.72,2669.92 2939.72,2901.26 2906.25,2934.73 2906.25,3310.32 2708,3508.57 2708,3533.75 2681.05,3560.7
  Bottom Layer w4: 2203,3879.81 2234,3879.81 2239.72,3885.53 2278.17,3885.53 U29.J2@2290.89,3898.25 ; 2214.24,3841.81 2224.94,3841.81 2243.06,3859.93 2278.17,3859.93 U29.H2@2290.89,3872.66
  Bottom Layer w7: 1704.86,2063.21 1704.86,2080.95 ; 2217.96,3993.41 2218.62,3992.75 2236.35,3975.02 U29.M1@2265.3,3975.02 ; U29.U12@2546.8,4102.97 2546.8,4176.81 2552.55,4182.57 v1(2552.55,4202.81) C164.2@2552.55,4228.46
  Bottom Layer w8: U29.F18@2700.34,3821.48 U29.F19@2725.93,3821.48
  Bottom Layer w10: U11.8@1529.02,1987.85 1551.99,1987.85 1587.95,2023.81 1665.46,2023.81 1704.86,2063.21 ; R47.1@1698.44,1998.09 1718.94,1977.59 1761,1977.59 1771.4,1987.99 R60.2@1771.4,2022.99 ; v1(1954,1615.81) 1954,1617.98 1966.21,1630.18 R67.2@1966.21,1658.96 ; C111.2@2146,3799.81 2150.84,3804.65 2162.14,3804.65 2199.3,3841.81 2214.24,3841.81 ; C107.2@2146,3835.75 C107.2@2146.5,3836.25 ; v1(2147,3855.81) 2146.5,3855.31 C107.2@2146.5,3836.25 ; 2189,4013.95 2197.42,4013.95 2217.96,3993.41 ; 2203,3879.81 2162.81,3839.62 2149.88,3839.62 C107.2@2146.5,3836.25 ; C110.1@2293.44,3540.12 2293.44,3551.34 2303.28,3561.18 2303.28,3623.28 2342.07,3662.07 U29.A4@2342.07,3693.52 ; U29.A12@2546.8,3693.52 2546.8,3661.33 2581.7,3626.43 v1(2581.7,3609.48) 2581.7,3607.31 2574.41,3600.03 2574.41,3585.41 C163.2@2570.08,3581.08 ; U29.F18@2700.34,3821.48 U29.G18@2700.34,3847.07 ; U29.F19@2725.93,3821.48 U29.F20@2751.52,3821.48 2806.28,3821.48 v1(2823.89,3803.87) ; U29.U19@2725.93,4102.97 2748.78,4125.82 2748.78,4184.49 2755.76,4191.47 C165.2@2755.76,4181.93 ; U29.L20@2751.52,3949.43 2752.09,3949.99 2802.31,3949.99 2802.5,3949.8 2813.29,3949.8 2817.28,3945.81 C170.2@2853.32,3945.81 2853.57,3945.81 2858.41,3950.65 v1(2858.41,3971.89) ; C165.2@2753.34,4186.31 2753.34,4184.35 2758.18,4179.5 2760.52,4179.5 2766.38,4173.65 2766.38,4160.53 v1(2767.91,4159)
  Bottom Layer w12: C111.2@2146.36,3798.2 2146.36,3779.67 v1(2146.72,3779.31)
  Bottom Layer w14: C112.1@2052,4023.79 2061.84,4013.95 C5.2@2107,4013.95 C113.2@2145.52,4013.95 2189,4013.95
  other v1: 1751,2060.81 1780,2060.81 1809,2060.81 1751,2086.81 1780,2086.81 1809,2086.81 2239.68,3528.83 2239.68,3556.83 1990.24,4021.93 1990.24,4045.51 2014,4045.51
